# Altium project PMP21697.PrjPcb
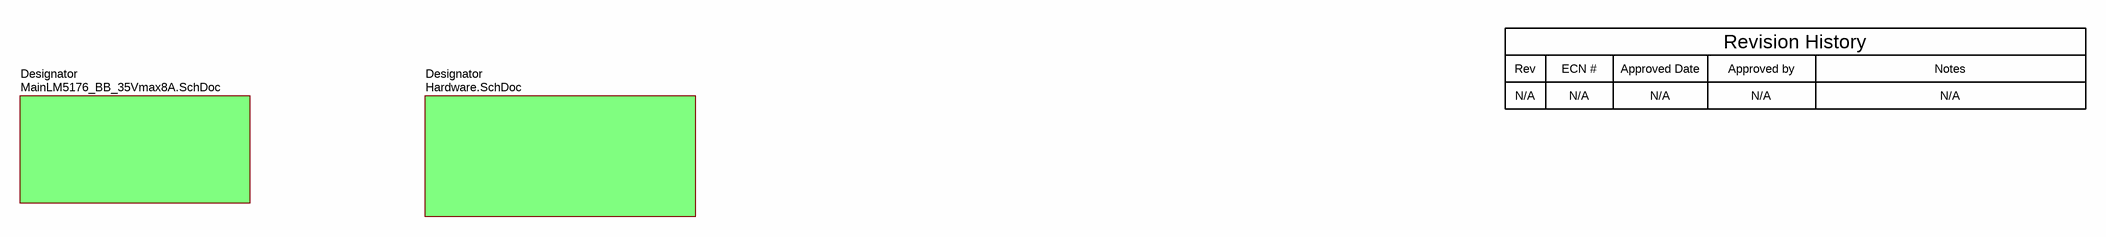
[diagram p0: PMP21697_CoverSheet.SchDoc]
TID: N/A; TechSupport: http://www.ti.com/support; SCH_Rev: A; PRJ_Title: Power for Automotive Audio Amplifiers; PRJ_Number: PMP21697; PRJ_Engineer: Josh Mandelcorn; PCB_Rev: A; PCB_Layout: Krypton; EVM_orderable: no; CopyrightYear: 2019
3 sheets, 163 parts. Net scope: flat (ports and power ports of the same name join across sheets).
Board file: PMP21697_PCB.PcbDoc
Sheets:
  PMP21697_CoverSheet.SchDoc
    Designator = MainLM5176_BB_35Vmax8A.SchDoc
    Designator = Hardware.SchDoc

## Sheet PMP21697_CoverSheet.SchDoc: CoverSheet
size 431 x 279 mm; Date: Not shown in title block; ApprovedBy: Not shown in title block; CheckedBy: Not shown in title block; Author: Not shown in title block; CompanyName: Not shown in title block; DrawnBy: Josh Mandelcorn; Engineer: Not shown in title block; Organization: Not shown in title block; Address1: Not shown in title block; Address2: Not shown in title block; Address3: Not shown in title block; Address4: Not shown in title block; DocumentNumber: 1; Revision: Use project parameter SCH_Rev; SheetNumber: 1; SheetTotal: 3; PageSetup: Record=PageOptions¦CenterHorizontal=True¦CenterVertical=True¦PrintScale=1.00¦XCorrection=1.00¦YCorrection=1.00¦PrintKind=0¦BorderSize=5000000¦LeftOffset=0¦BottomOffset=0¦Orientation=2¦PaperLength=1000¦PaperWidth=1000¦Scale=100¦PaperSource=15¦PrintQuality=600¦MediaType=1¦DitherType=10¦PaperKind=Letter¦PrintScaleMode=1

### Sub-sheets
Designator = MainLM5176_BB_35Vmax8A.SchDoc: no entries
Designator = Hardware.SchDoc: no entries

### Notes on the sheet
- Rev
- N/A
- ECN #
- Approved Date
- Approved by
- Revision History
- Notes

## Sheet MainLM5176_BB_35Vmax8A.SchDoc: PMP21697
size 431 x 279 mm; Date: Not shown in title block; ApprovedBy: Not shown in title block; CheckedBy: Not shown in title block; Author: Not shown in title block; CompanyName: Not shown in title block; DrawnBy: Josh Mandelcorn; Engineer: Not shown in title block; Organization: Not shown in title block; Address1: Not shown in title block; Address2: Not shown in title block; Address3: Not shown in title block; Address4: Not shown in title block; DocumentNumber: 2; Revision: Use project parameter SCH_Rev; SheetNumber: 2; SheetTotal: 3; PageSetup: Record=PageOptions¦CenterHorizontal=True¦CenterVertical=True¦PrintScale=1.00¦XCorrection=1.00¦YCorrection=1.00¦PrintKind=0¦BorderSize=5000000¦LeftOffset=0¦BottomOffset=0¦Orientation=2¦PaperLength=1000¦PaperWidth=1000¦Scale=100¦PaperSource=15¦PrintQuality=600¦MediaType=1¦DitherType=10¦PaperKind=Letter¦PrintScaleMode=1
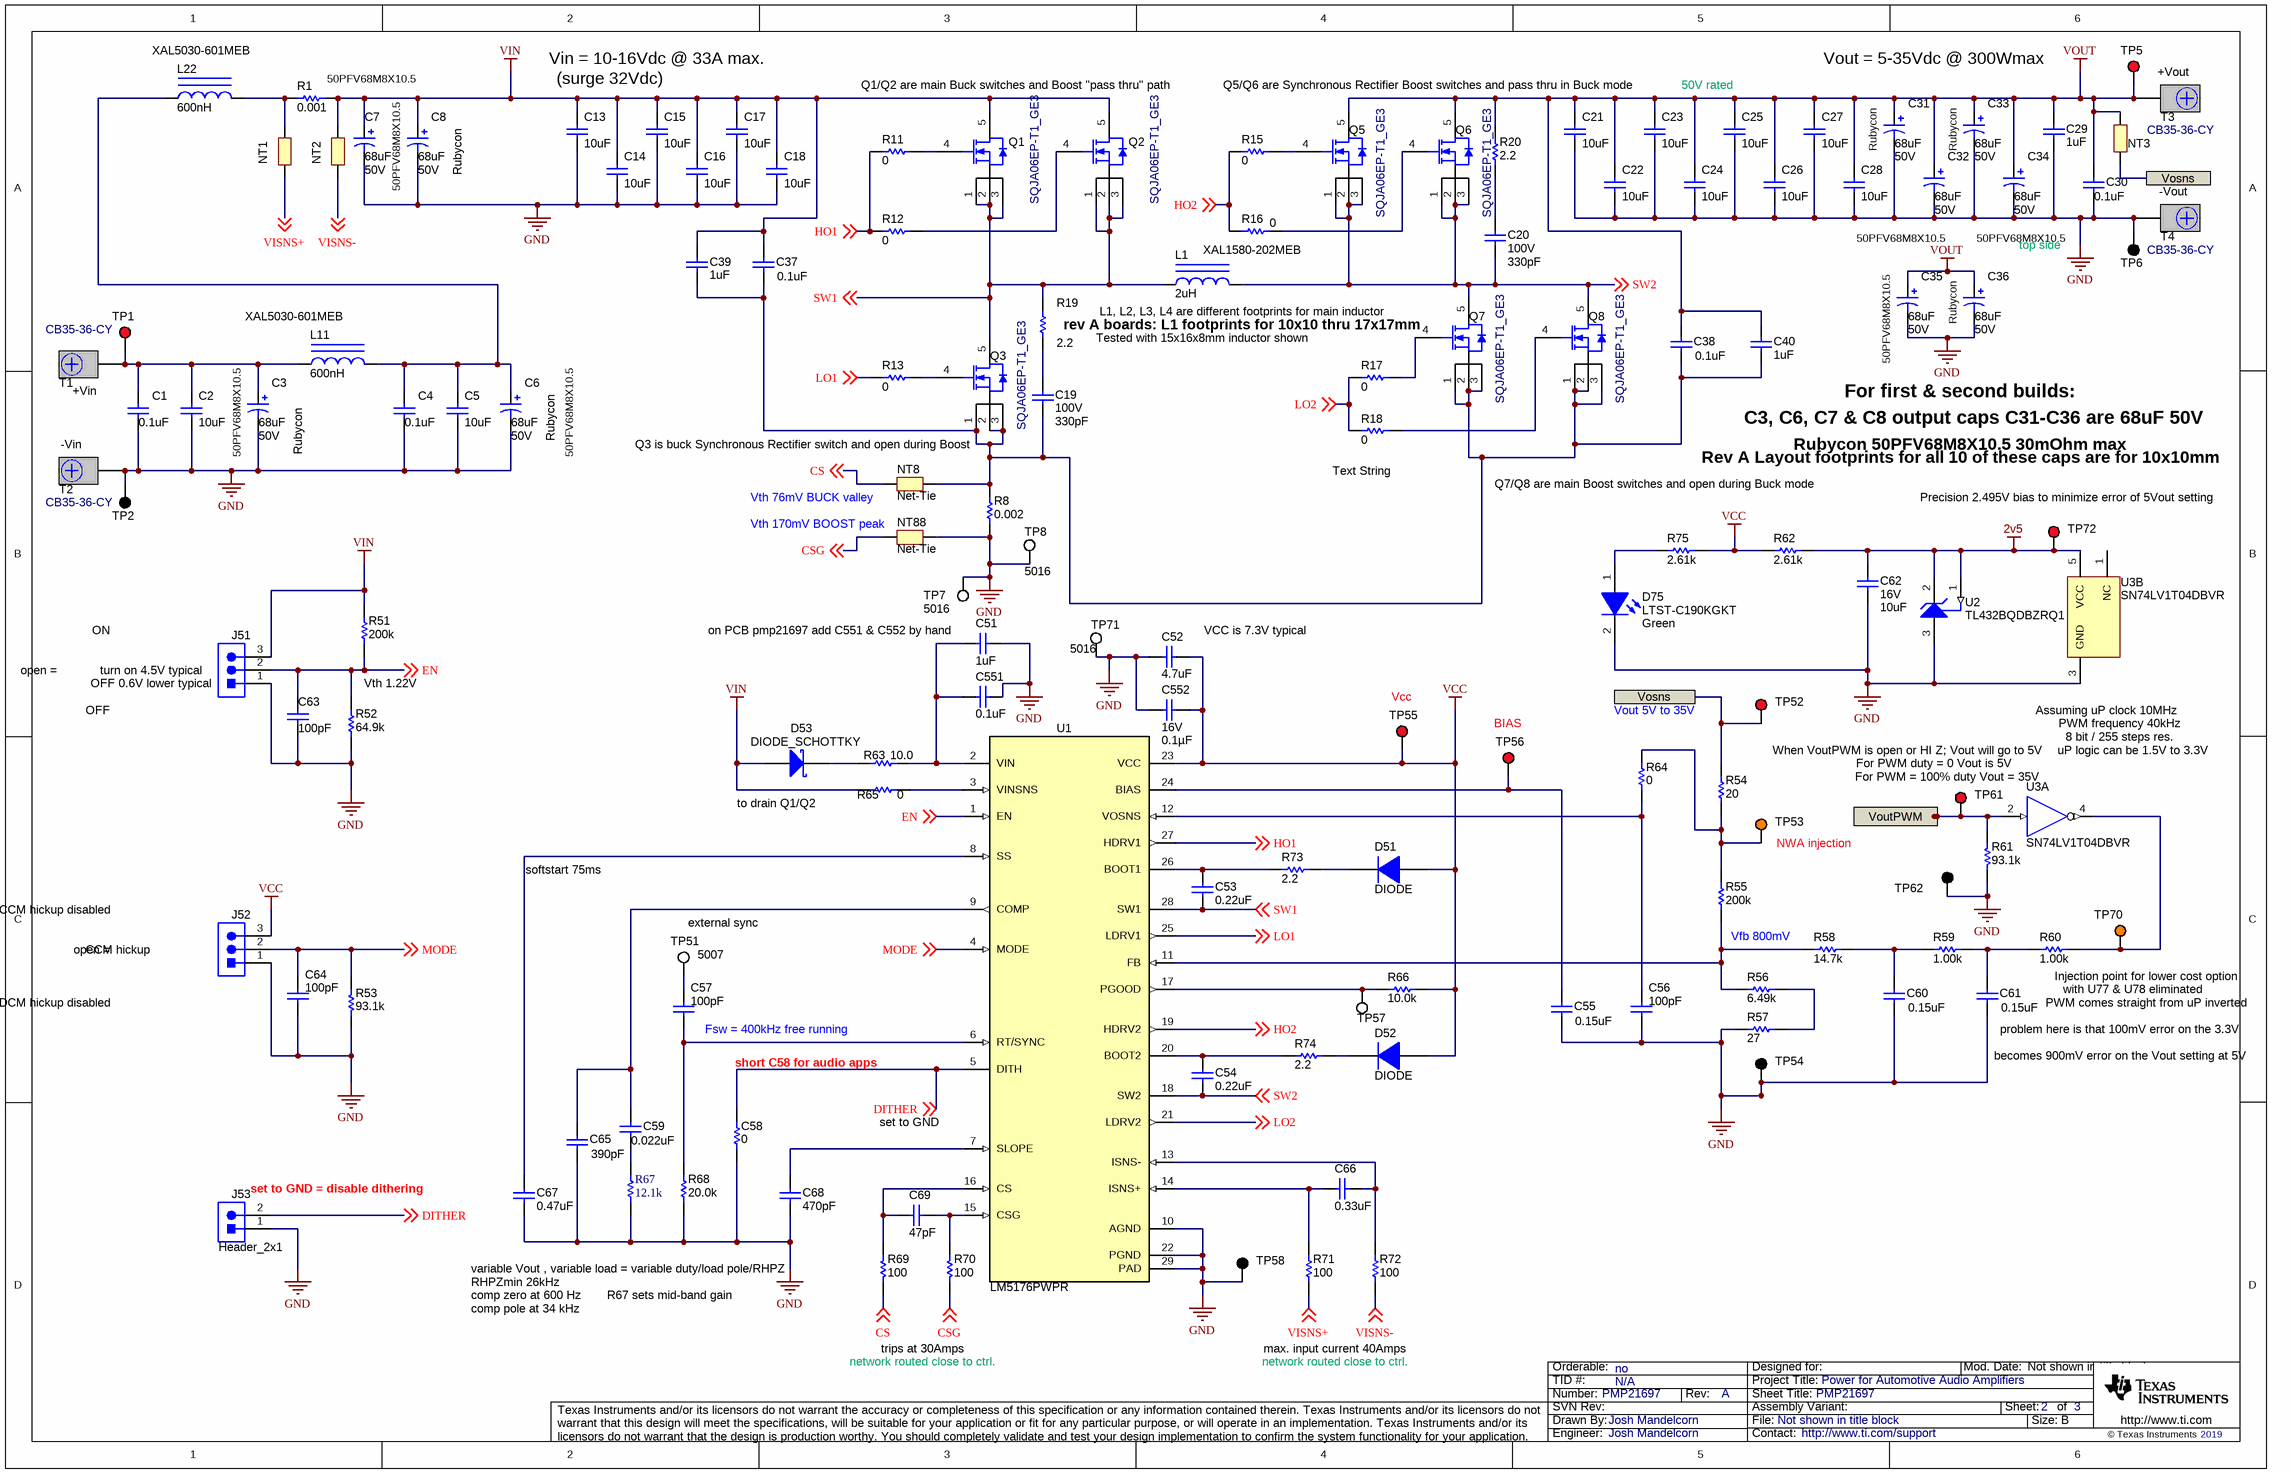
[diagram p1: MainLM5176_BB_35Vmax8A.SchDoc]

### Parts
C1  ValueDisplayed: 0.1uF  [0603L]  (hidden comment: Capacitor)
C2  ValueDisplayed: 10uF  [1210_270]  (hidden comment: Capacitor)
C3  50PFV68M8X10.5  ValueDisplayed: 68uF  Value2: 50V  [SM_RADIAL_10BMM]
C4  ValueDisplayed: 0.1uF  [0603L]  (hidden comment: Capacitor)
C5  ValueDisplayed: 10uF  [1210_270]  (hidden comment: Capacitor)
C6  50PFV68M8X10.5  ValueDisplayed: 68uF  Value2: 50V  [SM_RADIAL_10BMM]
C7  50PFV68M8X10.5  ValueDisplayed: 68uF  Value2: 50V  [SM_RADIAL_10BMM]
C8  50PFV68M8X10.5  ValueDisplayed: 68uF  Value2: 50V  [SM_RADIAL_10BMM]
C13  ValueDisplayed: 10uF  [1210_270]  (hidden comment: Capacitor)
C14  ValueDisplayed: 10uF  [1210_270]  (hidden comment: Capacitor)
C15  ValueDisplayed: 10uF  [1210_270]  (hidden comment: Capacitor)
C16  ValueDisplayed: 10uF  [1210_270]  (hidden comment: Capacitor)
C17  ValueDisplayed: 10uF  [1210_270]  (hidden comment: Capacitor)
C18  ValueDisplayed: 10uF  [1210_270]  (hidden comment: Capacitor)
C19  VDC_V: 100V  ValueDisplayed: 330pF  [0805_HV]  (hidden comment: 08051C331KAT2A)
C20  VDC_V: 100V  ValueDisplayed: 330pF  [0805_HV]  (hidden comment: 08051C331KAT2A)
C21  ValueDisplayed: 10uF  [1210_270]  (hidden comment: Capacitor)
C22  ValueDisplayed: 10uF  [1210_270]  (hidden comment: Capacitor)
C23  ValueDisplayed: 10uF  [1210_270]  (hidden comment: Capacitor)
C24  ValueDisplayed: 10uF  [1210_270]  (hidden comment: Capacitor)
C25  ValueDisplayed: 10uF  [1210_270]  (hidden comment: Capacitor)
C26  ValueDisplayed: 10uF  [1210_270]  (hidden comment: Capacitor)
C27  ValueDisplayed: 10uF  [1210_270]  (hidden comment: Capacitor)
C28  ValueDisplayed: 10uF  [1210_270]  (hidden comment: Capacitor)
C29  ValueDisplayed: 1uF  [0805_HV]  (hidden comment: Capacitor)
C30  ValueDisplayed: 0.1uF  [0603L]  (hidden comment: Capacitor)
C31  Rubycon  ValueDisplayed: 68uF  Value2: 50V  [SM_RADIAL_10BMM]
C32  50PFV68M8X10.5  ValueDisplayed: 68uF  Value2: 50V  [SM_RADIAL_10BMM]
C33  Rubycon  ValueDisplayed: 68uF  Value2: 50V  [SM_RADIAL_10BMM]
C34  50PFV68M8X10.5  ValueDisplayed: 68uF  Value2: 50V  [SM_RADIAL_10BMM]
C35  50PFV68M8X10.5  ValueDisplayed: 68uF  Value2: 50V  [SM_RADIAL_10BMM]
C36  Rubycon  ValueDisplayed: 68uF  Value2: 50V  [SM_RADIAL_10BMM]
C37  ValueDisplayed: 0.1uF  [0603L]  (hidden comment: Capacitor)
C38  ValueDisplayed: 0.1uF  [0603L]  (hidden comment: Capacitor)
C39  ValueDisplayed: 1uF  [0805_HV]  (hidden comment: Capacitor)
C40  ValueDisplayed: 1uF  [0805_HV]  (hidden comment: Capacitor)
C51  ValueDisplayed: 1uF  [0603]  (hidden comment: Capacitor)
C52  ValueDisplayed: 4.7uF  [0805_HV]  (hidden comment: Capacitor)
C53  ValueDisplayed: 0.22uF  [0603L]  (hidden comment: Capacitor)
C54  ValueDisplayed: 0.22uF  [0603L]  (hidden comment: Capacitor)
C55  ValueDisplayed: 0.15uF  [0603]  (hidden comment: CGA3E3X7R1H154K080AB)
C56  ValueDisplayed: 100pF  [0603]  (hidden comment: Capacitor)
C57  ValueDisplayed: 100pF  [0603]  (hidden comment: Capacitor)
C58  value 0  [0603L]  (hidden comment: Resistor)
C59  ValueDisplayed: 0.022uF  [0402]  (hidden comment: GCM155R71E223KA55D)
C60  ValueDisplayed: 0.15uF  [0603]  (hidden comment: CGA3E3X7R1H154K080AB)
C61  ValueDisplayed: 0.15uF  [0603]  (hidden comment: CGA3E3X7R1H154K080AB)
C62  VDC_V: 16V  ValueDisplayed: 10uF  [0805_HV]  (hidden comment: GCM21BC71C106KE36L)
C63  ValueDisplayed: 100pF  [0603]  (hidden comment: Capacitor)
C64  ValueDisplayed: 100pF  [0603]  (hidden comment: Capacitor)
C65  ValueDisplayed: 390pF  [0402]  (hidden comment: GCM155R71H391KA37D)
C66  ValueDisplayed: 0.33uF  [0603L]  (hidden comment: Capacitor)
C67  ValueDisplayed: 0.47uF  [0603L]  (hidden comment: Capacitor)
C68  ValueDisplayed: 470pF  [0402]  (hidden comment: GCM155R71H471KA37D)
C69  ValueDisplayed: 47pF  [0603]  (hidden comment: Capacitor)
C551  ValueDisplayed: 0.1uF  [0603L]  (hidden comment: Capacitor)
C552  VDC_V: 16V  ValueDisplayed: 0.1µF  [0402]  (hidden comment: GCM155R71C104JA55D)
D51  DIODE  [SOD-323]
D52  DIODE  [SOD-323]
D53  DIODE_SCHOTTKY  [SOD-323F]
D75  LTST-C190KGKT  value Green  [LED_LTST-C190_G]
J51  Header_3x1_Launchpad  [CONN_PEC03SAAN]  (value not drawn)
J52  Header_3x1_Launchpad  [CONN_PEC03SAAN]  (value not drawn)
J53  Header_2x1  [CONN_PEC02SAAN]
L1  XAL1580-202MEB  ValueDisplayed: 2uH  [XAL1580]
L11  XAL5030-601MEB  ValueDisplayed: 600nH  [XAL5030]
L22  XAL5030-601MEB  ValueDisplayed: 600nH  [XAL5030]
NT1  Net-Tie  [Net-Tie_10mil]  (value not drawn)  (net tie, no BOM)
NT2  Net-Tie  [Net-Tie_10mil]  (value not drawn)  (net tie, no BOM)
NT3  Net-Tie  [Net-Tie_10mil]  (value not drawn)  (net tie, no BOM)
NT8  Net-Tie  [Net-Tie_10mil]  (net tie, no BOM)
NT88  Net-Tie  [Net-Tie_10mil]  (net tie, no BOM)
Q1  SQJA06EP-T1_GE3  [PowerPAK_SO-8L]
Q2  SQJA06EP-T1_GE3  [PowerPAK_SO-8L]
Q3  SQJA06EP-T1_GE3  [PowerPAK_SO-8L]
Q5  SQJA06EP-T1_GE3  [PowerPAK_SO-8L]
Q6  SQJA06EP-T1_GE3  [PowerPAK_SO-8L]
Q7  SQJA06EP-T1_GE3  [PowerPAK_SO-8L]
Q8  SQJA06EP-T1_GE3  [PowerPAK_SO-8L]
R1  ValueDisplayed: 0.001  [2512_WIDE]  (hidden comment: PML100HZPJV1L5)
R8  ValueDisplayed: 0.002  [2512_WIDE]  (hidden comment: FCSL64R002GER)
R11  value 0  [0603L]  (hidden comment: Resistor)
R12  value 0  [0603L]  (hidden comment: Resistor)
R13  value 0  [0603L]  (hidden comment: Resistor)
R15  value 0  [0603L]  (hidden comment: Resistor)
R16  value 0  [0603L]  (hidden comment: Resistor)
R17  value 0  [0603L]  (hidden comment: Resistor)
R18  value 0  [0603L]  (hidden comment: Resistor)
R19  ValueDisplayed: 2.2  [1206]  (hidden comment: CRCW12062R20JNEA)
R20  ValueDisplayed: 2.2  [1206]  (hidden comment: CRCW12062R20JNEA)
R51  ValueDisplayed: 200k  [0603]  (hidden comment: CRCW0603200KFKEA)
R52  ValueDisplayed: 64.9k  [0603]  (hidden comment: CRCW060364K9FKEA)
R53  ValueDisplayed: 93.1k  [0603L]  (hidden comment: Resistor)
R54  ValueDisplayed: 20  [0402]  (hidden comment: CRCW040220R0JNED)
R55  ValueDisplayed: 200k  [0603]  (hidden comment: CRCW0603200KFKEA)
R56  ValueDisplayed: 6.49k  [0603]  (hidden comment: CRCW06036K49FKEA)
R57  ValueDisplayed: 27  [0603]  (hidden comment: CRCW060327R0JNEA)
R58  ValueDisplayed: 14.7k  [0603]  (hidden comment: CRCW060314K7FKEA)
R59  ValueDisplayed: 1.00k  [0603]  (hidden comment: CRCW06031K00FKEA)
R60  ValueDisplayed: 1.00k  [0603]  (hidden comment: CRCW06031K00FKEA)
R61  ValueDisplayed: 93.1k  [0603L]  (hidden comment: Resistor)
R62  ValueDisplayed: 2.61k  [0603]  (hidden comment: CRCW06032K61FKEA)
R63  value 10.0  [0603]  (hidden comment: Resistor)
R64  value 0  [0603L]  (hidden comment: Resistor)
R65  value 0  [0603L]  (hidden comment: Resistor)
R66  value 10.0k  [0603]  (hidden comment: Resistor)
R67  12.1k  [RESC1005X40X25LL05T05]
R68  ValueDisplayed: 20.0k  [0603]  (hidden comment: CRCW060320K0FKEA)
R69  value 100  [0603_HV]  (hidden comment: Resistor)
R70  value 100  [0603_HV]  (hidden comment: Resistor)
R71  value 100  [0603L]  (hidden comment: Resistor)
R72  value 100  [0603L]  (hidden comment: Resistor)
R73  ValueDisplayed: 2.2  [0402]  (hidden comment: CRCW04022R20JNED)
R74  ValueDisplayed: 2.2  [0402]  (hidden comment: CRCW04022R20JNED)
R75  ValueDisplayed: 2.61k  [0603]  (hidden comment: CRCW06032K61FKEA)
T1  CB35-36-CY  [CB35-36-CY]
T2  CB35-36-CY  [CB35-36-CY]
T3  CB35-36-CY  [CB35-36-CY]
T4  CB35-36-CY  [CB35-36-CY]
TP1  5005  [Keystone5005]  (value not drawn)
TP2  5006  [Keystone5006]  (value not drawn)
TP5  5005  [Keystone5005]  (value not drawn)
TP6  5006  [Keystone5006]  (value not drawn)
TP7  5016  [Testpoint_Keystone_Compact]
TP8  5016  [Testpoint_Keystone_Compact]
TP51  5007  [Keystone5007]
TP52  5000  [Keystone5000]  (value not drawn)
TP53  5003  [Keystone5003]  (value not drawn)
TP54  5001  [Keystone5001]  (value not drawn)
TP55  5000  [Keystone5000]  (value not drawn)
TP56  5000  [Keystone5000]  (value not drawn)
TP57  5007  [Keystone5007]  (value not drawn)
TP58  5001  [Keystone5001]  (value not drawn)
TP61  5000  [Keystone5000]  (value not drawn)
TP62  5001  [Keystone5001]  (value not drawn)
TP70  5003  [Keystone5003]  (value not drawn)
TP71  5016  [Testpoint_Keystone_Compact]
TP72  5000  [Keystone5000]  (value not drawn)
U1  LM5176PWPR  [PWP0028C_N]
U2  TL432BQDBZRQ1  [DBZ0003A_N]
U3  SN74LV1T04DBVR  [DBV0005A_N]  (parts A,B of 2)

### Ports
Vosns, VoutPWM (in)

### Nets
2v5: C62.1 R62.2 TP72.1 U2.1(REF) U2.2(CATHODE) U3.5(VCC)
GND: C1.2 C2.2 C3.2(-) C4.2 C5.2 C6.2(-) C7.2(-) C8.2(-) C13.2 C14.2 C15.2 C16.2 C17.2 C18.2 C21.2 C22.2 C23.2 C24.2 C25.2 C26.2 C27.2 C28.2 C29.2 C30.2 C31.2(-) C32.2(-) C33.2(-) C34.2(-) C35.2(-) C36.2(-) C51.2 C52.1 C55.2 C56.1 C58.2 C60.2 C61.2 C62.2 C63.1 C64.1 C65.2 C67.2 C68.2 C551.2 C552.2 D75.2(K) J51.1 J52.1 J53.1 NT88.2 R8.1 R52.1 R53.1 R57.1 R61.1 R67.1 R68.1 T2.1 T4.1 TP2.1 TP6.1 TP7.1 TP8.1 TP54.1 TP58.1 TP62.1 TP71.1 U1.10(AGND) U1.22(PGND) U1.29(PAD) U2.3(ANODE) U3.3(GND)
VCC: C52.2 C552.1 D51.2(A) D52.2(A) J52.3 R62.1 R66.2 R75.2 TP55.1 U1.23(VCC)
VIN: C7.1(+) C8.1(+) C13.1 C14.1 C15.1 C16.1 C17.1 C18.1 C37.1 C39.1 D53.2(A) J51.3 NT2.2 Q1.5(D) Q2.5(D) R1.2 R51.2 R65.2
VOUT: C21.1 C22.1 C23.1 C24.1 C25.1 C26.1 C27.1 C28.1 C29.1 C30.1 C31.1(+) C32.1(+) C33.1(+) C34.1(+) C35.1(+) C36.1(+) C38.1 C40.1 NT3.1 Q5.5(D) Q6.5(D) R20.2 T3.1 TP5.1
CS: NT8.1 R69.1 ; off-sheet CS
CSG: NT88.1 R70.1 ; off-sheet CSG
DITHER: C58.1 J53.2 U1.5(DITH) ; off-sheet DITHER
EN: C63.2 J51.2 R51.1 R52.2 U1.1(EN) ; off-sheet EN
HO1: R11.2 R12.2 U1.27(HDRV1) ; off-sheet HO1
HO2: R15.2 R16.2 U1.19(HDRV2) ; off-sheet HO2
LO1: R13.2 U1.25(LDRV1) ; off-sheet LO1
LO2: R17.2 R18.2 U1.21(LDRV2) ; off-sheet LO2
MODE: C64.2 J52.2 R53.2 U1.4(MODE) ; off-sheet MODE
SW1: C53.1 L1.1 Q1.1(S) Q1.2(S) Q1.3(S) Q2.1(S) Q2.2(S) Q2.3(S) Q3.5(D) R19.2 U1.28(SW1) ; off-sheet SW1
SW2: C20.2 C54.2 L1.2 Q5.1(S) Q5.2(S) Q5.3(S) Q6.1(S) Q6.2(S) Q6.3(S) Q7.5(D) Q8.5(D) U1.18(SW2) ; off-sheet SW2
VISNS+: NT1.1 R71.1 ; off-sheet VISNS+
VISNS-: NT2.1 R72.1 ; off-sheet VISNS-
Vosns: NT3.2 R54.2 TP52.1 ; port Vosns
VoutPWM: R61.2 TP61.1 U3.2(A) ; port VoutPWM
NetC1_1: C1.1 C2.1 C3.1(+) L11.1 T1.1 TP1.1
NetC4_1: C4.1 C5.1 C6.1(+) L11.2 L22.1
NetC19_1: C19.1 R19.1
NetC19_2: C19.2 C37.2 C38.2 C39.2 C40.2 NT8.2 Q3.1(S) Q3.2(S) Q3.3(S) Q7.1(S) Q7.2(S) Q7.3(S) Q8.1(S) Q8.2(S) Q8.3(S) R8.2
NetC20_1: C20.1 R20.1
NetC51_1: C51.1 C551.1 R63.1 U1.2(VIN)
NetC53_2: C53.2 R73.1 U1.26(BOOT1)
NetC54_1: C54.1 R74.1 U1.20(BOOT2)
NetC55_1: C55.1 TP56.1 U1.24(BIAS)
NetC56_2: C56.2 R64.2 U1.12(VOSNS)
NetC57_1: C57.1 R68.2 U1.6(RT/SYNC)
NetC57_2: C57.2 TP51.1
NetC59_1: C59.1 C65.1 U1.9(COMP)
NetC59_2: C59.2 R67.2
NetC60_1: C60.1 R58.2 R59.1
NetC61_1: C61.1 R59.2 R60.1
NetC66_1: C66.1 R71.2 U1.14(ISNS+)
NetC66_2: C66.2 R72.2 U1.13(ISNS-)
NetC67_1: C67.1 U1.8(SS)
NetC68_1: C68.1 U1.7(SLOPE)
NetC69_1: C69.1 R69.2 U1.16(CS)
NetC69_2: C69.2 R70.2 U1.15(CSG)
NetD51_1: D51.1(K) R73.2
NetD52_1: D52.1(K) R74.2
NetD53_1: D53.1(K) R63.2
NetD75_1: D75.1(A) R75.1
NetL22_2: L22.2 NT1.2 R1.1
NetQ1_4: Q1.4(G) R11.1
NetQ2_4: Q2.4(G) R12.1
NetQ3_4: Q3.4(G) R13.1
NetQ5_4: Q5.4(G) R15.1
NetQ6_4: Q6.4(G) R16.1
NetQ7_4: Q7.4(G) R17.1
NetQ8_4: Q8.4(G) R18.1
NetR54_1: R54.1 R55.2 R64.1 TP53.1
NetR55_1: R55.1 R56.2 R58.1 U1.11(FB)
NetR56_1: R56.1 R57.2
NetR60_2: R60.2 TP70.1 U3.4(Y)
NetR65_1: R65.1 U1.3(VINSNS)
NetR66_1: R66.1 TP57.1 U1.17(PGOOD)

Not connected (* = marked no-connect by the designer): U3 1(NC)

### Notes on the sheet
- (surge 32Vdc)
- Vin = 10-16Vdc @ 33A max.
- Q1/Q2 are main Buck switches and Boost "pass thru" path
- Q5/Q6 are Synchronous Rectifier Boost switches and pass thru in Buck mode
- 50V rated
- Vout = 5-35Vdc @ 300Wmax
- +Vout
- (near C8) Rubycon
- (near T4) -Vout
- top side
- Tested with 15x16x8mm inductor shown
- L1, L2, L3, L4 are different footprints for main inductor
- rev A boards: L1 footprints for 10x10 thru 17x17mm
- (near T1) +Vin
- Rubycon
- (near C6) Rubycon
- For first & second builds:
- C3, C6, C7 & C8 output caps C31-C36 are 68uF 50V
- (near T2) -Vin
- Vth 76mV BUCK valley
- Q3 is buck Synchronous Rectifier switch and open during Boost
- (near R18) Text String
- Q7/Q8 are main Boost switches and open during Buck mode
- Rubycon 50PFV68M8X10.5 30mOhm max
- Rev A Layout footprints for all 10 of these caps are for 10x10mm
- (near TP72) Precision 2.495V bias to minimize error of 5Vout setting
- Vth 170mV BOOST peak
- ON
- on PCB pmp21697 add C551 & C552 by hand
- (near C52) VCC is 7.3V typical
- open =
- (near J51) turn on 4.5V typical
- (near J51) OFF 0.6V lower typical
- Vth 1.22V
- (near TP55) Vcc
- OFF
- (near TP56) BIAS
- Vout 5V to 35V
- When VoutPWM is open or HI Z; Vout will go to 5V
- For PWM duty = 0 Vout is 5V
- (near U3) Assuming uP clock 10MHz
- PWM frequency 40kHz
- 8 bit / 255 steps res.
- uP logic can be 1.5V to 3.3V
- to drain Q1/Q2
- For PWM = 100% duty Vout = 35V
- softstart 75ms
- (near TP53) NWA injection
- (near J52) CCM hickup disabled
- (near J52) CCM hickup
- (near TP51) external sync
- Vfb 800mV
- (near J52) DCM hickup disabled
- (near C57) Fsw = 400kHz free running
- (near C61) problem here is that 100mV error on the 3.3V
- with U77 & U78 eliminated
- Injection point for lower cost option
- PWM comes straight from uP inverted
- short C58 for audio apps
- (near C61) becomes 900mV error on the Vout setting at 5V
- (near U1) set to GND
- (near J53) set to GND = disable dithering
- variable Vout , variable load = variable duty/load pole/RHPZ
- RHPZmin 26kHz
- comp zero at 600 Hz
- R67 sets mid-band gain
- comp pole at 34 kHz
- trips at 30Amps
- network routed close to ctrl.
- max. input current 40Amps

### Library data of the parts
C1 C4 C30 C37 C38 C551 = CMP-0007469-4: CAP, CERM, 0.1 uF, 100 V, +/- 10%, X7R, 0603; PartNumber: GRM188R72A104KA35D; Manufacturer: MuRata; Polarized: N; Value: 0.1uF; U/M: EA; Cap_F: 100nF; Value1: Unknown; VDC_V: 100V; TaMin_C: -55°C; TaMax_C: 125°C; Cap_Case: 0603; AEC Category: Q200; SizeArea_mm2: 1.28; SizeAreaWB_mm2: 4.68; SizeX_mm: 1.6; SizeY_mm: 0.8; SizeZ_mm: 1
C2 C5 C13-C18 C21-C28 = CMP-0009226-3: CAP, CERM, 10 uF, 50 V, +/- 10%, X7R, 1210; PartNumber: GRM32ER71H106KA12L; Manufacturer: MuRata; Value: 10uF; U/M: EA; VDC_V: 50V; Polarized: N; Cap_F: 10µF; Value1: Unknown; TaMin_C: -55°C; TaMax_C: 125°C; Cap_Case: 1210; AEC Category: Q200; SizeArea_mm2: 8; SizeAreaWB_mm2: 14.7; SizeX_mm: 3.2; SizeY_mm: 2.5; SizeZ_mm: 2.7
C3 C6-C8 C31-C36 = CMP-0012596-3: CAP, Polymer Hybrid, 100 uF, 50 V, +/- 20%, 28 ohm, 10x10 SMD; PartNumber: EEHZC1H101P; Manufacturer: Panasonic; Polarized: Y; CompType: Capacitor; Value: 100uF; Cap_F: 100µF; Value1: 28 ohm; ESR_ohm: 28; IRMS_A: 1.6A; TaMin_C: -55°C; TaMax_C: 125°C; AEC Category: Q200; SizeArea_mm2: 113.3; SizeAreaWB_mm2: 159.9; SizeX_mm: 11; SizeY_mm: 10.3; SizeZ_mm: 10.2
C19 C20 = CMP-0007553-2: CAP, CERM, 330 pF, 100 V, +/- 10%, X7R, 0805; Manufacturer: AVX; TaMin_C: -55°C; ESR_ohm: 5.63d; Polarized: N; SizeAreaWB_mm2: 6.75; Value1: 0.563 ohm; U/M: EA; Value: 330pF; TaMax_C: 125°C; SizeZ_mm: 1.45; SizeX_mm: 2; SizeY_mm: 1.25; Cap_Case: 0805; SizeArea_mm2: 2.5; AEC Category: Q200
C29 C39 C40 = CMP-0008350-2: CAP, CERM, 1 uF, 50 V, +/- 10%, X7R, 0805; PartNumber: GRM21BR71H105KA12L; Manufacturer: MuRata; Polarized: N; Value: 1uF; U/M: EA; Cap_F: 1µF; Value1: Unknown; VDC_V: 50V; TaMin_C: -55°C; TaMax_C: 125°C; Cap_Case: 0805; AEC Category: Q200; SizeArea_mm2: 2.5; SizeAreaWB_mm2: 6.75; SizeX_mm: 2; SizeY_mm: 1.25; SizeZ_mm: 1.45
C51 = CMP-0007350-5: CAP, CERM, 1 uF, 50 V, +/- 10%, X5R, 0603; PartNumber: GRM188R61H105KAALD; Manufacturer: MuRata; Polarized: N; Value: 1uF; U/M: EA; Cap_F: 1µF; Value1: Unknown; VDC_V: 50V; TaMin_C: -55°C; TaMax_C: 85°C; AEC Category: Q200; SizeArea_mm2: 1.28; SizeAreaWB_mm2: 4.68; SizeX_mm: 1.6; SizeY_mm: 0.8; SizeZ_mm: 1
C52 = CMP-0008334-2: CAP, CERM, 4.7 uF, 16 V, +/- 10%, X7R, 0805; PartNumber: GRM21BR71C475KA73L; Manufacturer: MuRata; Polarized: N; Value: 4.7uF; U/M: EA; Cap_F: 4.7µF; ESR_ohm: 6m; Value1: 0.006 ohm; VDC_V: 16V; TaMin_C: -55°C; TaMax_C: 125°C; Cap_Case: 0805; AEC Category: Q200; SizeArea_mm2: 2.5; SizeAreaWB_mm2: 6.75; SizeX_mm: 2; SizeY_mm: 1.25; SizeZ_mm: 1.45
C53 C54 = CMP-0007415-4: CAP, CERM, 0.22 uF, 25 V, +/- 10%, X7R, 0603; PartNumber: GRM188R71E224KA88D; Manufacturer: MuRata; Polarized: N; Value: 0.22uF; U/M: EA; Cap_F: 220nF; Value1: Unknown; VDC_V: 25V; TaMin_C: -55°C; TaMax_C: 125°C; Cap_Case: 0603; AEC Category: Q200; SizeArea_mm2: 1.28; SizeAreaWB_mm2: 4.68; SizeX_mm: 1.6; SizeY_mm: 0.8; SizeZ_mm: 1
C55 C60 C61 = CMP-0007093-5: CAP, CERM, 0.15 uF, 50 V, +/- 10%, X7R, AEC-Q200 Grade 1, 0603; Manufacturer: TDK; TaMin_C: -55°C; ESR_ohm: 0.028863; Polarized: N; SizeAreaWB_mm2: 4.68; Value1: 0.028863 ohm; U/M: EA; Value: 0.15uF; TaMax_C: 125°C; SizeZ_mm: 1; SizeX_mm: 1.6; SizeY_mm: 0.8; Value2: 50V; SizeArea_mm2: 1.28; CompType: Capacitor; AEC Qualified: Y; Cap_F: 150nF; IRMS_A: 9.78809dA; AEC Category: Q200
C56 C57 C63 C64 = CMP-0007237-4: CAP, CERM, 100 pF, 100 V, +/- 5%, C0G/NP0, 0603; PartNumber: GRM1885C2A101JA01D; Manufacturer: MuRata; Polarized: N; Value: 100pF; U/M: EA; Value1: Unknown; VDC_V: 100V; TaMin_C: -55°C; TaMax_C: 125°C; AEC Category: Q200; SizeArea_mm2: 1.28; SizeAreaWB_mm2: 4.68; SizeX_mm: 1.6; SizeY_mm: 0.8; SizeZ_mm: 1
C58 R11-R13 R15-R18 R64 R65 = CMP-0025885-5: RES, 0, 5%, 0.1 W, 0603; PartNumber: RC0603JR-070RL; Manufacturer: Yageo; Value_Code: 0000; Power_W: 100mW; Value2: 0.1W; VDC_V: 75V; TempCo: 200 ppm/C; EIA_Code: E24; AEC Category: Q200; AEC Qualified: N; SizeArea_mm2: 1.28; SizeAreaWB_mm2: 4.68; SizeX_mm: 1.6; SizeY_mm: 0.8; SizeZ_mm: 1
C59 = CMP-0006353-2: CAP, CERM, 0.022 uF, 25 V, +/- 10%, X7R, AEC-Q200 Grade 1, 0402; Manufacturer: MuRata; TaMin_C: -55°C; Polarized: N; SizeAreaWB_mm2: 3; Value1: Unknown; U/M: EA; TaMax_C: 125°C; SizeZ_mm: 0.6; SizeX_mm: 1; SizeY_mm: 0.5; Value2: 25V; AEC Qualified: Y; Cap_F: 22nF; AEC Category: Q200
C62 = CMP-0008012-2: CAP, CERM, 10 uF, 16 V, +/- 10%, X7S, AEC-Q200 Grade 1, 0805; Manufacturer: MuRata; TaMin_C: -55°C; Polarized: N; SizeAreaWB_mm2: 6.75; Value1: Unknown; U/M: EA; Value: 10uF; TaMax_C: 125°C; SizeZ_mm: 1.45; SizeX_mm: 2; SizeY_mm: 1.25; Cap_Case: 0805; SizeArea_mm2: 2.5; CompType: Capacitor; AEC Qualified: Y; Cap_F: 10µF; AEC Grade: 1; AEC Category: Q200
C65 = CMP-0080703-2: CAP, CERM, 390 pF, 50 V,+/- 10%, X7R, AEC-Q200 Grade 1, 0402; Manufacturer: MuRata; SizeX_mm: 1; SizeZ_mm: 0.6; SizeY_mm: 0.5; AEC Qualified: Y; Value: 390pF; Polarized: N; AEC Category: Q200; TaMax_C: 125°C; VDC_V: 50V; TaMin_C: -55°C; SizeAreaWB_mm2: 3; U/M: EA
C66 = CMP-0007393-4: CAP, CERM, 0.33 uF, 16 V, +/- 10%, X7R, 0603; PartNumber: GRM188R71C334KA01D; Manufacturer: MuRata; Polarized: N; Value: 0.33uF; U/M: EA; Cap_F: 330nF; Value1: Unknown; VDC_V: 16V; TaMin_C: -55°C; TaMax_C: 125°C; Cap_Case: 0603; AEC Category: Q200; SizeArea_mm2: 1.28; SizeAreaWB_mm2: 4.68; SizeX_mm: 1.6; SizeY_mm: 0.8; SizeZ_mm: 1
C67 = CMP-0007398-4: CAP, CERM, 0.47 uF, 16 V, +/- 10%, X7R, 0603; PartNumber: GRM188R71C474KA88D; Manufacturer: MuRata; Polarized: N; Value: 0.47uF; U/M: EA; Cap_F: 470nF; Value1: Unknown; VDC_V: 16V; TaMin_C: -55°C; TaMax_C: 125°C; Cap_Case: 0603; AEC Category: Q200; SizeArea_mm2: 1.28; SizeAreaWB_mm2: 4.68; SizeX_mm: 1.6; SizeY_mm: 0.8; SizeZ_mm: 1
C68 = CMP-0006360-2: CAP, CERM, 470 pF, 50 V, +/- 10%, X7R, AEC-Q200 Grade 1, 0402; Manufacturer: MuRata; TaMin_C: -55°C; Polarized: N; SizeAreaWB_mm2: 3; Value1: Unknown; U/M: EA; Value: 470pF; TaMax_C: 125°C; SizeZ_mm: 0.6; SizeX_mm: 1; SizeY_mm: 0.5; Value2: 50V; AEC Qualified: Y; AEC Category: Q200
C69 = CMP-0007220-4: CAP, CERM, 47 pF, 50 V, +/- 5%, C0G/NP0, 0603; PartNumber: GRM1885C1H470JA01D; Manufacturer: MuRata; Polarized: N; Value: 47pF; U/M: EA; Value1: Unknown; VDC_V: 50V; TaMin_C: -55°C; TaMax_C: 125°C; AEC Category: Q200; SizeArea_mm2: 1.28; SizeAreaWB_mm2: 4.68; SizeX_mm: 1.6; SizeY_mm: 0.8; SizeZ_mm: 1
C552 = CMP-0080702-1: CAP, CERM, 0.1 µF, 16 V,+/- 5%, X7R, AEC-Q200 Grade 1, 0402; Manufacturer: MuRata; Cap_F: 100nF; SizeAreaWB_mm2: 3; SizeArea_mm2: 0.5; AEC Qualified: Y; AEC Category: Q200; Value: 0.1uF; TaMax_C: 125°C; SizeZ_mm: 0.6; AEC Grade: 1; Polarized: N; TaMin_C: -55°C; U/M: EA
D51 D52 = CMP-0029006-1: Diode, Ultrafast, 100 V, 0.25 A, SOD-323; Manufacturer: Nexperia; PartNumber: BAS316,115; U/M: EA; Vr_V: 100V; Value: 100V; Io_A: 2.5dA; Vf_V: 1.4V; Value1: 0.25A; TJmax_C: 150°C; AEC Category: Q101; Green_Lifecycle: Not Set; Green_REACh: Incomplete; SizeArea_mm2: 3.645; SizeAreaWB_mm2: 8.695; SizeX_mm: 2.7; SizeY_mm: 1.35; SizeZ_mm: 1
D53 = CMP-0077011-1: Diode, Schottky, 60 V, 1 A, SOD-323F; PartNumber: PMEG6010CEJ,115; Manufacturer: Nexperia; U/M: EA; Vf_V: 6.6dV; Value: 60V; Value1: 1A; Value2: 0.66V; TJmax_C: 150°C; AEC Category: Q101; Green_Lifecycle: Not Set; Green_REACh: Incomplete; SizeArea_mm2: 3.125; SizeAreaWB_mm2: 7.875; SizeX_mm: 2.5; SizeY_mm: 1.25; SizeZ_mm: 0.8
D75 = CMP-0002840-1: LED, Green, SMD; Manufacturer: Lite-On; Io_A: 30mA; Tjmax_C: 85°C; Value1: W; U/M: EA; Vf_V: 2V; Type: AlInGaP
J51 J52 = CMP-0002338-1: Header, 100mil, 3x1, Tin, TH; PartNumber: PEC03SAAN; Manufacturer: Sullins Connector Solutions; Cert_UL: Y; CNHeader: TRUE; CT: FALSE; Current_A: 3A; Gender: Male; Green_Lifecycle: Not Set; Green_REACh: Incomplete; Pitch_mm: 2.54; Row_Count: 1; Shrouded: N; Voltage_V: 1.8kV
J53 = CMP-0002337-1: Header, 100mil, 2x1, Tin, TH; PartNumber: PEC02SAAN; Manufacturer: Sullins Connector Solutions; Cert_UL: Y; CNHeader: TRUE; CT: FALSE; Current_A: 3A; Gender: Male; Green_Lifecycle: Not Set; Green_REACh: Incomplete; Pitch_mm: 2.54; Row_Count: 1; Shrouded: N; Voltage_V: 1.8kV
L1 = CMP-0060976-1: Inductor, Shielded, Composite, 2 uH, 39.9 A, 0.001909 ohm, SMD; Manufacturer: Coilcraft; Isat: 51A @ 0.7% inductance drop; Irms: 39.9A @ 40C rise; Green_Lifecycle: Not Set; SizeAreaWB_mm2: 313.04; DCR_ohm: 1.909m; Green_REACh: Incomplete; Value: 2uH; Imax_A: 39.9A; SizeZ_mm: 8; SizeX_mm: 15.2; SizeY_mm: 16.2; SizeArea_mm2: 246.24; Ind_H: 2µH; AEC Category: Q200
L11 L22 = CMP-0061005-2: Inductor, Shielded, Composite, 600 nH, 17.7 A, 0.00411 ohm, AEC-Q200 Grade 1, SMD; Manufacturer: Coilcraft; Isat: 19.8A @ 30% inductance drop; Irms: 17.7A @ 40C rise; Green_Lifecycle: Not Set; SizeAreaWB_mm2: 54.4544; DCR_ohm: 4.11m; Green_REACh: Incomplete; Value: 600nH; Imax_A: 17.7A; SizeZ_mm: 3.1; SizeX_mm: 5.28; SizeY_mm: 5.48; SizeArea_mm2: 28.9344; AEC Qualified: 1; AEC Category: Q200; AEC Grade: Y
NT1-NT3 NT8 NT88 = CMP-0078142-2: Single point connection between nets.
Q1-Q3 Q5-Q8 = CMP-0077287-1: MOSFET, N-CH, 60 V, 57 A, AEC-Q101, PowerPAK_SO-8L; Manufacturer: Vishay-Siliconix; Alternate Manufacturer: None; ChType: N; QgTyp_nC: 27.0; SizeAreaWB_mm2: 58.1095; SizeArea_mm2: 31.5495; IdsMax_A: 57A; AEC Qualified: Y; VdsMax_V: 60V; Vgs_V: 20V; AEC Category: Q101; Value: 60V; SizeZ_mm: 1.14; SizeY_mm: 5.13; Value2: 27 nC; U/M: EA; Value1: ? ohm; SizeX_mm: 6.15
R1 = CMP-0084409-1: RES, 0.0015, 5%, 2 W, 2512 WIDE; Manufacturer: Rohm; Value_Code: 1L500; Res_ohm: 1.5m; AEC Qualified: N; Value: 0.0015; SizeArea_mm2: 20.16; SizeY_mm: 6.3; SizeAreaWB_mm2: 43.16; AEC Category: Q200; Power_W: 2W; SizeX_mm: 3.2; TempCo: 100 ppm/C; SizeZ_mm: 0.7
R8 = CMP-0015353-2: RES, 0.002, 2%, 2 W, 2512 WIDE; Manufacturer: Ohmite; Power_W: 2W; TempCo: 100 ppm/C; SizeAreaWB_mm2: 43.16; Value_Code: 2L000; U/M: EA; Value: 0.002; Res_ohm: 2m; SizeX_mm: 3.2; SizeY_mm: 6.3; SizeZ_mm: 0.7; SizeArea_mm2: 20.16; CompType: Resistor; AEC Category: Q200
R19 = CMP-0018649-3: RES, 2.2, 5%, 0.25 W, AEC-Q200 Grade 0, 1206; Manufacturer: Vishay-Dale; Power_W: 250mW; TempCo: 200 ppm/C; Value_Code: 2R20; Value: 2.2; EIA_Code: E24; SizeX_mm: 3.2; SizeY_mm: 1.6; SizeZ_mm: 1.35; Value2: 0.25W; SizeArea_mm2: 5.12; CompType: Resistor; AEC Qualified: Y; VDC_V: 200V; AEC Category: Q200; AEC Grade: 0
R20 = CMP-0018649-3: RES, 2.2, 5%, 0.25 W, AEC-Q200 Grade 0, 1206; Manufacturer: Vishay-Dale; Power_W: 250mW; TempCo: 200 ppm/C; Value_Code: 2R20; Value: 2.2; EIA_Code: E24; SizeX_mm: 3.2; SizeY_mm: 1.6; SizeZ_mm: 1.35; Value2: 0.25W; SizeArea_mm2: 5.12; AEC Qualified: Y; VDC_V: 200V; AEC Category: Q200; AEC Grade: 0
R51 R55 = CMP-0022200-4: RES, 200 k, 1%, 0.1 W, AEC-Q200 Grade 0, 0603; Manufacturer: Vishay-Dale; Power_W: 100mW; TempCo: 100 ppm/C; Value: 200k; EIA_Code: E96; SizeX_mm: 1.6; SizeY_mm: 0.8; SizeZ_mm: 1; Value2: 0.1W; SizeArea_mm2: 1.28; AEC Qualified: Y; VDC_V: 75V; AEC Category: Q200; AEC Grade: 0
R52 = CMP-0022544-4: RES, 64.9 k, 1%, 0.1 W, AEC-Q200 Grade 0, 0603; Manufacturer: Vishay-Dale; Power_W: 100mW; TempCo: 100 ppm/C; Value_Code: 64k9; Value: 64.9k; EIA_Code: E96; SizeX_mm: 1.6; SizeY_mm: 0.8; SizeZ_mm: 1; Value2: 0.1W; SizeArea_mm2: 1.28; AEC Qualified: Y; VDC_V: 75V; AEC Category: Q200; AEC Grade: 0
R53 R61 = CMP-0023322-5: RES, 93.1 k, 1%, 0.1 W, 0603; PartNumber: RC0603FR-0793K1L; Manufacturer: Yageo; Value: 93.1k; Value_Code: 93k1; Power_W: 100mW; Value2: 0.1W; VDC_V: 75V; TempCo: 100 ppm/C; EIA_Code: E96; AEC Category: Q200; AEC Qualified: N; SizeArea_mm2: 1.28; SizeAreaWB_mm2: 4.68; SizeX_mm: 1.6; SizeY_mm: 0.8; SizeZ_mm: 1
R54 = CMP-0026876-3: RES, 20, 5%, 0.063 W, AEC-Q200 Grade 0, 0402; Manufacturer: Vishay-Dale; Power_W: 63mW; TempCo: 200 ppm/C; Value_Code: 20R0; Value: 20; EIA_Code: E24; SizeX_mm: 1; SizeY_mm: 0.5; SizeZ_mm: 0.6; Value2: 0.063W; AEC Qualified: Y; VDC_V: 50V; AEC Category: Q200; AEC Grade: 0
R56 = CMP-0022561-4: RES, 6.49 k, 1%, 0.1 W, AEC-Q200 Grade 0, 0603; Manufacturer: Vishay-Dale; Power_W: 100mW; TempCo: 100 ppm/C; Value_Code: 6k49; Value: 6.49k; EIA_Code: E96; SizeX_mm: 1.6; SizeY_mm: 0.8; SizeZ_mm: 1; Value2: 0.1W; SizeArea_mm2: 1.28; AEC Qualified: Y; VDC_V: 75V; AEC Category: Q200; AEC Grade: 0
R57 = CMP-0025767-4: RES, 27, 5%, 0.1 W, AEC-Q200 Grade 0, 0603; Manufacturer: Vishay-Dale; Power_W: 100mW; TempCo: 200 ppm/C; Value_Code: 27R0; Value: 27; EIA_Code: E24; SizeX_mm: 1.6; SizeY_mm: 0.8; SizeZ_mm: 1; Value2: 0.1W; SizeArea_mm2: 1.28; AEC Qualified: Y; VDC_V: 75V; AEC Category: Q200; AEC Grade: 0
R58 = CMP-0022056-4: RES, 14.7 k, 1%, 0.1 W, AEC-Q200 Grade 0, 0603; Manufacturer: Vishay-Dale; Power_W: 100mW; TempCo: 100 ppm/C; Value_Code: 14k7; Value: 14.7k; EIA_Code: E96; SizeX_mm: 1.6; SizeY_mm: 0.8; SizeZ_mm: 1; Value2: 0.1W; SizeArea_mm2: 1.28; AEC Qualified: Y; VDC_V: 75V; AEC Category: Q200; AEC Grade: 0
R59 R60 = CMP-0022109-5: RES, 1.00 k, 1%, 0.1 W, AEC-Q200 Grade 0, 0603; Manufacturer: Vishay-Dale; Power_W: 100mW; TempCo: 100 ppm/C; Value_Code: 1k00; Value: 1.00k; EIA_Code: E96; Res_ohm: 1k; SizeX_mm: 1.6; SizeY_mm: 0.8; SizeZ_mm: 1; Value2: 0.1W; SizeArea_mm2: 1.28; AEC Qualified: Y; VDC_V: 75V; AEC Category: Q200; AEC Grade: 0
R62 R75 = CMP-0022279-4: RES, 2.61 k, 1%, 0.1 W, AEC-Q200 Grade 0, 0603; Manufacturer: Vishay-Dale; Power_W: 100mW; TempCo: 100 ppm/C; Value_Code: 2k61; Value: 2.61k; EIA_Code: E96; SizeX_mm: 1.6; SizeY_mm: 0.8; SizeZ_mm: 1; Value2: 0.1W; SizeArea_mm2: 1.28; AEC Qualified: Y; VDC_V: 75V; AEC Category: Q200; AEC Grade: 0
R63 = CMP-0022751-4: RES, 10.0, 1%, 0.1 W, 0603; PartNumber: RC0603FR-0710RL; Manufacturer: Yageo; Res_ohm: 10; Value_Code: 10R0; Power_W: 100mW; Value2: 0.1W; VDC_V: 75V; TempCo: 100 ppm/C; EIA_Code: E96; AEC Category: Q200; AEC Qualified: N; SizeArea_mm2: 1.28; SizeAreaWB_mm2: 4.68; SizeX_mm: 1.6; SizeY_mm: 0.8; SizeZ_mm: 1
R66 = CMP-0022746-5: RES, 10.0 k, 1%, 0.1 W, 0603; PartNumber: RC0603FR-0710KL; Manufacturer: Yageo; Res_ohm: 10k; Value_Code: 10k0; Power_W: 100mW; Value2: 0.1W; VDC_V: 75V; TempCo: 100 ppm/C; EIA_Code: E96; AEC Category: Q200; AEC Qualified: N; SizeArea_mm2: 1.28; SizeAreaWB_mm2: 4.68; SizeX_mm: 1.6; SizeY_mm: 0.8; SizeZ_mm: 1
R67 = CMP-2002-08179-3: Chip Resistor, 12.1 KOhm, +/- 1%, 63 mW, -55 to 155 degC, 0402 (1005 Metric), RoHS, Tape and Reel; Manufacturer: Basic Passives; PartNumber: CRCW040212K1FKED; Power Rating: 63 mW; Voltage Rating: 50 V; Case\/Package: 0402
R68 = CMP-0022204-4: RES, 20.0 k, 1%, 0.1 W, AEC-Q200 Grade 0, 0603; Manufacturer: Vishay-Dale; Power_W: 100mW; TempCo: 100 ppm/C; Value_Code: 20k0; Value: 20.0k; EIA_Code: E96; Res_ohm: 20k; SizeX_mm: 1.6; SizeY_mm: 0.8; SizeZ_mm: 1; Value2: 0.1W; SizeArea_mm2: 1.28; AEC Qualified: Y; VDC_V: 75V; AEC Category: Q200; AEC Grade: 0
R69-R72 = CMP-0022736-4: RES, 100, 1%, 0.1 W, 0603; PartNumber: RC0603FR-07100RL; Manufacturer: Yageo; Value_Code: 100R; Power_W: 100mW; Value2: 0.1W; VDC_V: 75V; TempCo: 100 ppm/C; EIA_Code: E96; AEC Category: Q200; AEC Qualified: N; SizeArea_mm2: 1.28; SizeAreaWB_mm2: 4.68; SizeX_mm: 1.6; SizeY_mm: 0.8; SizeZ_mm: 1
R73 R74 = CMP-0026898-2: RES, 2.2, 5%, 0.063 W, 0402; Manufacturer: Vishay-Dale; Power_W: 63mW; TempCo: 200 ppm/C; Value_Code: 2R20; U/M: EA; Value: 2.2; EIA_Code: E24; SizeX_mm: 1; SizeY_mm: 0.5; SizeZ_mm: 0.6; Value2: 0.063W; VDC_V: 50V; AEC Category: Q200
T1-T4 = CMP-0055442-1: Terminal 50A Lug; Manufacturer: Panduit; CompType: Screw Terminal; Cert_CULUS: Y; CNHeader: FALSE; ContactFinish: Copper; Green_Lifecycle: Not Set; Green_REACh: Incomplete; Voltage_V: 600V
TP1 TP5 = CMP-0055142-1: Test Point, Compact, Red, TH; Manufacturer: Keystone; CNHeader: FALSE; ContactFinish: Silver; CT: TRUE; Green_Lifecycle: Active; Green_REACh: Passed
TP2 TP6 = CMP-0055143-1: Test Point, Compact, Black, TH; Manufacturer: Keystone; CNHeader: FALSE; ContactFinish: Silver; CT: TRUE; Green_Lifecycle: Active; Green_REACh: Passed
TP7 TP8 TP71 = CMP-0055153-1: Test Point, Compact, SMT; Manufacturer: Keystone; CNHeader: FALSE; Green_Lifecycle: Active; Green_REACh: Passed; CT: TRUE
TP51 TP57 = CMP-0055144-1: Test Point, Compact, White, TH; Manufacturer: Keystone; CNHeader: FALSE; ContactFinish: Silver; CT: TRUE; Green_Lifecycle: Active; Green_REACh: Passed
TP52 TP55 TP56 TP61 TP72 = CMP-0055137-1: Test Point, Miniature, Red, TH; Manufacturer: Keystone; CNHeader: FALSE; ContactFinish: Silver; CT: TRUE; Green_Lifecycle: Active; Green_REACh: Passed
TP53 TP70 = CMP-0055140-1: Test Point, Miniature, Orange, TH; Manufacturer: Keystone; CNHeader: FALSE; ContactFinish: Silver; CT: TRUE; Green_Lifecycle: Active; Green_REACh: Passed
TP54 TP58 TP62 = CMP-0055138-1: Test Point, Miniature, Black, TH; Manufacturer: Keystone; CNHeader: FALSE; ContactFinish: Silver; CT: TRUE; Green_Lifecycle: Active; Green_REACh: Passed
U1 = CMP-0013685-4: 55 V Wide VIN Synchronous 4-Switch Buck-Boost Controller, PWP0028C (TSSOP-28); Manufacturer: Texas Instruments; Alternate PartNumber: LM5176PWPT; SizeX_mm: 6.4; SizeY_mm: 9.7; CompType: IC; SizeZ_mm: 1.2; SizeArea_mm2: 62.08; SizeAreaWB_mm2: 98.28; AEC Category: Q200; AEC Qualified: N
U2 = CMP-0032978-1: Automotive Catalog Adjustable Precision Shunt Regulator, 34 ppm / degC, 100 mA, -40 to 125 degC, 3-pin SOT-23 (DBZ), Green (RoHS & no Sb/Br); Manufacturer: Texas Instruments; VO Adj(Min)(V): 2.495; Temp Coeff(Typ)(ppm/ degree C): 34; SubFamily: Shunt Voltage Reference; Initial Accuracy @ 25/deg C(%): 0.5; Min Iz for Regulation(uA): 600; VO Adj(Max)(V): 36; Iout/Iz(Max)(mA): 100
U3 = CMP-0051667-2: Single Power Supply INVERTER Gate logic level shifter, DBV0005A (SOT-23-5); Manufacturer: Texas Instruments; Rating: Catalog; ICC @ Nom Voltage(Max)(mA): 0.01; Input Type: TTL; Schmitt Trigger: No; VCC(Max)(V): 5.5; tpd @ Nom Voltage(Max)(ns): 13,7.5,5.5,7.0; Special Features: 1.8V to 3.3V Up Translation,3.3V to 1.8V Down Translation,5V Input Tolerant; Logic: Inverting; 3-State Output: Yes; F @ Nom Voltage(Max)(Mhz): 50; Voltage(Nom)(V): 1.8,2.5,3.3,5.5; Output Type: CMOS; VCC(Min)(V): 1.6; Bits(#): 1; Output Drive (IOL/IOH)(Max)(mA): 8/-8; AEC Category: Q200; AEC Qualified: N; CompType: IC; SizeAreaWB_mm2: 14.82; SizeArea_mm2: 8.12; SizeX_mm: 2.8; SizeY_mm: 2.9; SizeZ_mm: 1.45

## Sheet Hardware.SchDoc: Hardware
size 431 x 279 mm; Date: Not shown in title block; ApprovedBy: Not shown in title block; CheckedBy: Not shown in title block; Author: Not shown in title block; CompanyName: Not shown in title block; DrawnBy: Josh Mandelcorn; Engineer: Not shown in title block; Organization: Not shown in title block; Address1: Not shown in title block; Address2: Not shown in title block; Address3: Not shown in title block; Address4: Not shown in title block; DocumentNumber: 3; Revision: Use project parameter SCH_Rev; SheetNumber: 3; SheetTotal: 3; PageSetup: Record=PageOptions¦CenterHorizontal=True¦CenterVertical=True¦PrintScale=1.00¦XCorrection=1.00¦YCorrection=1.00¦PrintKind=0¦BorderSize=5000000¦LeftOffset=0¦BottomOffset=0¦Orientation=2¦PaperLength=1000¦PaperWidth=1000¦Scale=100¦PaperSource=15¦PrintQuality=600¦MediaType=1¦DitherType=10¦PaperKind=Letter¦PrintScaleMode=1
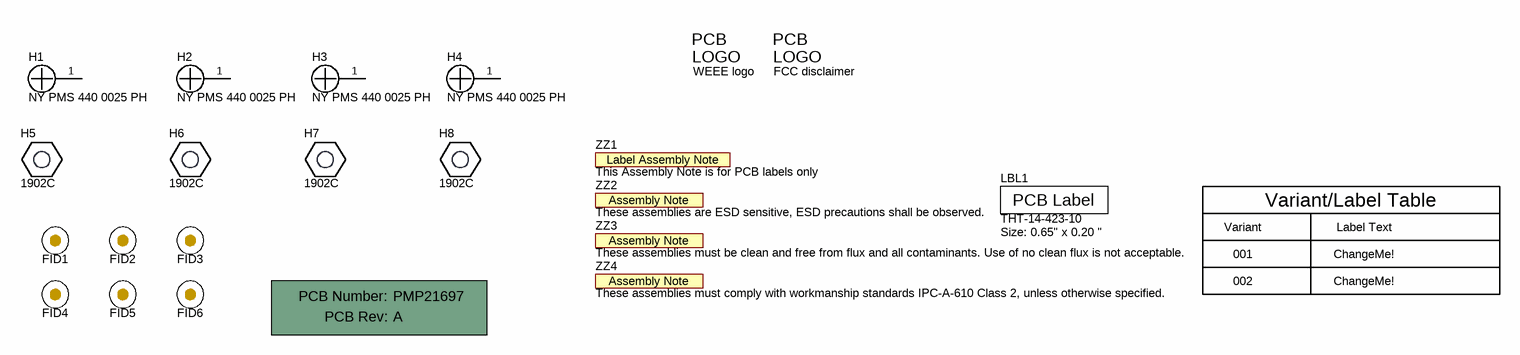
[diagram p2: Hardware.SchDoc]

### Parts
!PCB1  Printed Circuit Board  (value not drawn)  (mechanical)
FID1  Fiducial  [Fiducial10-20]  (value not drawn)
FID2  Fiducial  [Fiducial10-20]  (value not drawn)
FID3  Fiducial  [Fiducial10-20]  (value not drawn)
FID4  Fiducial  [Fiducial10-20]  (value not drawn)
FID5  Fiducial  [Fiducial10-20]  (value not drawn)
FID6  Fiducial  [Fiducial10-20]  (value not drawn)
H1  NY PMS 440 0025 PH  [NY PMS 440 0025 PH]
H2  NY PMS 440 0025 PH  [NY PMS 440 0025 PH]
H3  NY PMS 440 0025 PH  [NY PMS 440 0025 PH]
H4  NY PMS 440 0025 PH  [NY PMS 440 0025 PH]
H5  1902C  [Keystone_1902C]
H6  1902C  [Keystone_1902C]
H7  1902C  [Keystone_1902C]
H8  1902C  [Keystone_1902C]
LBL1  THT-14-423-10  Note: Size: 0.65" x 0.20 "  [Label_650x200]
Logo1  FCC disclaimer  [FCC_disclaimer]  (no BOM)
Logo2  WEEE logo  [WEEE_Minimum]  (no BOM)
ZZ1  This Assembly Note is for PCB labels only  [AssemblyNoteLabel]  (no BOM)
ZZ2  These assemblies are ESD sensitive, ESD precautions shall be observed.  [AssemblyNote]  (no BOM)
ZZ3  These assemblies must be clean and free from flux and all contaminants. Use of no clean flux is not acceptable.  [AssemblyNote]  (no BOM)
ZZ4  These assemblies must comply with workmanship standards IPC-A-610 Class 2, unless otherwise specified.  [AssemblyNote]  (no BOM)

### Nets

Not connected (* = marked no-connect by the designer): H1 1; H2 1; H3 1; H4 1

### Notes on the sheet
- Variant/Label Table
- Variant
- 001
- Label Text
- ChangeMe!
- 002

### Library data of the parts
!PCB1 = CMP-0003618-2: Manufacturer: Any; PartNumber: PMP21697
FID1-FID6 = CMP-0077181-1: Fiducial mark.  There is nothing to buy or mount.
H1-H4 = CMP-0003617-1: Machine Screw, Round, #4-40 x 1/4, Nylon, Philips panhead; Manufacturer: B&F Fastener Supply; CompType: Hardware
H5-H8 = CMP-0003610-1: Standoff, Hex, 0.5"L #4-40 Nylon; Manufacturer: Keystone; CompType: Hardware
LBL1 = CMP-0003625-1: Thermal Transfer Printable Labels, 0.650" W x 0.200" H - 10,000 per roll; Manufacturer: Brady; CompType: Label
Logo1 = CMP-0074847-1: FCC_disclaimer; Library Reference: Logo
Logo2 = CMP-0074769-1
ZZ1 = CMP-0003616-3
ZZ2 = CMP-0077236-1
ZZ3 = CMP-0077237-1
ZZ4 = CMP-0077238-1

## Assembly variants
001: not fitted FID1 FID2 FID3 FID4 FID5 FID6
